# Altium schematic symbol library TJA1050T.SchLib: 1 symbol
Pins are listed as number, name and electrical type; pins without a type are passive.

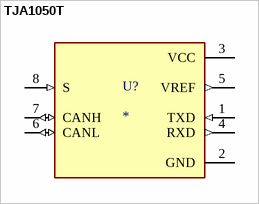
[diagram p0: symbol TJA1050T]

## TJA1050T
designator U?
1/1 Transceiver Half CANbus 8-SO; MF: NXP USA; MP: TJA1050T/CM,118
footprint TJA1050T
pins: 1 TXD (in), 2 GND (power), 3 VCC (power), 4 RXD (out), 5 VREF (out), 6 CANL (io), 7 CANH (io), 8 S (in)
